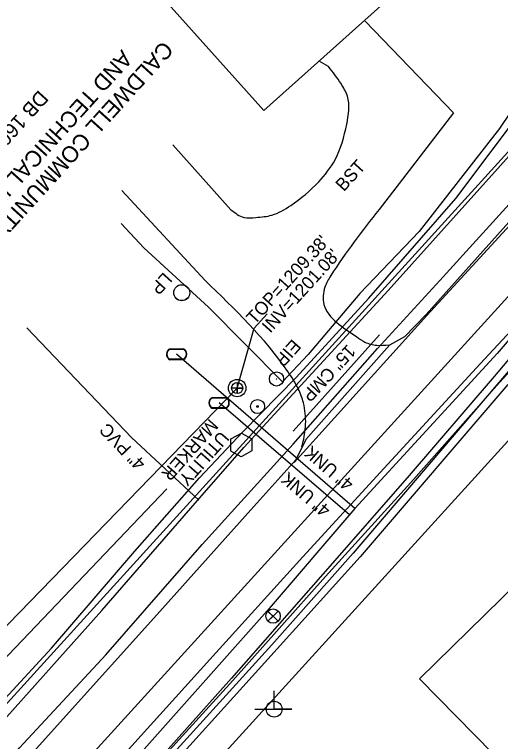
# Model space of a CAD drawing. Extents: x 1263837 to 1268319, y 770628 to 773628.
# Drawn here: x 1267189.7 to 1267339.7, y 772645 to 772869.3 of the extents above; entities that cross this region are included whole.
import ezdxf

# ---------------------------------------------------------------- set-up
doc = ezdxf.new("R2010")
doc.units = 0
for name, color, linetype in [('CTL Primary Horizontal and Vertical CELL', 7, 'Continuous'), ('Exist Building', 7, 'Continuous'), ('Exist Property Deed Book Text', 7, 'Continuous'), ('Exist Property Iron Pin Text', 7, 'Continuous'), ('Exist Roads EOT Text', 7, 'Continuous'), ('Exist Utilities Gas UG Line SUE LOS B', 7, 'Continuous'), ('Exist Utilities Gas UG Line SUE LOS B Text', 7, 'Continuous'), ('Exist Utilities Other Located Object CELL', 7, 'Continuous'), ('Exist Utilities Other Located Object Text', 7, 'Continuous'), ('Exist Utilities Other Pole CELL', 7, 'Continuous'), ('Exist Utilities Other Pole With Base Text', 7, 'Continuous'), ('Exist Utilities Power Joint Use Telephone CELL', 7, 'Continuous'), ('Exist Utilities Power UG Cable SUE LOS B', 7, 'Continuous'), ('Exist Utilities Telephone UG Cable SUE LOS B', 7, 'Continuous'), ('Exist Utilities Telephone UG FO SUE LOS B', 7, 'Continuous'), ('Exist Utilities Water Meter CELL', 7, 'Continuous'), ('Exist Utilities Water UG Line SUE LOS B', 7, 'Continuous'), ('Exist Utilities Water UG Line SUE LOS B Text', 7, 'Continuous'), ('Exist Utilities Water Valve CELL', 7, 'Continuous'), ('Pattern 2', 7, 'Continuous'), ('Prop Conc 4in Sidewalk', 7, 'Continuous'), ('Prop Drainage Structure Pipe RCP 15in Class III Label', 7, 'Continuous'), ('Prop Drainage Structure Pipe RCP 24in Class III Label', 7, 'Continuous'), ('Prop Earthen Structure Base Ditch Special Cut with Rip Rap Detail CELL', 7, 'Continuous'), ('Prop Horizontal Alignment', 7, 'Continuous'), ('Prop Retaining Wall', 7, 'Continuous'), ('Prop SS Fill Text', 7, 'Continuous'), ('Prop SS Transition Line', 7, 'Continuous'), ('Prop WCR CELL', 7, 'Continuous'), ('Scratch_Level_2', 7, 'Continuous'), ('Scratch_Level_5', 7, 'Continuous')]:
    doc.layers.add(name, color=color, linetype=linetype)

# ---------------------------------------------------------------- blocks, each defined once
blk = doc.blocks.new('EXIST UTILITIES SANITARY SEWER MANHOLE')
at = {"layer": 'Prop WCR CELL'}
blk.add_lwpolyline([(0, 0.03425), (0, -0.03425), (0, 0), (0.03425, 0), (-0.03425, 0)], dxfattribs=at)
for radius in [0.05389, 0.03425]:
    blk.add_circle((0, 0), radius, dxfattribs=at)
blk = doc.blocks.new('EXIST PROPERTY IRON PIN')
at = {"layer": 'Prop Conc 4in Sidewalk'}
for radius in [0.0441, 0.00141]:
    blk.add_circle((0, 0), radius, dxfattribs=at)
blk = doc.blocks.new('EXIST UTILITIES OTHER POLE')
at = {"layer": 'Exist Utilities Other Pole CELL'}
blk.add_circle((0, 0), 0.0493, dxfattribs=at)
blk = doc.blocks.new('EXIST UTILITIES POWER JOINT USE TELEPHONE')
at = {"layer": 'Exist Utilities Power Joint Use Telephone CELL'}
blk.add_line((0, 0), (0, 0), dxfattribs=at)
blk.add_lwpolyline([(-0.1188, 0), (0.108, -0.0008), (0, -0.0004), (0, 0.1125)], dxfattribs=at)
blk.add_circle((0, 0.0001), 0.049, dxfattribs=at)
blk = doc.blocks.new('EXIST UTILITIES WATER METER')
at = {"layer": 'Exist Utilities Water Meter CELL'}
blk.add_line((0, 0), (0, 0), dxfattribs=at)
for points in [[(-0.0408, 0.034), (0.0408, 0.034)], [(-0.0408, 0.0312), (0.0408, 0.0312)], [(0.0408, -0.0312), (-0.0413, -0.0312)], [(0.0408, -0.034), (-0.0413, -0.034)]]:
    blk.add_lwpolyline(points, dxfattribs=at)
for centre, radius, start, end in [((-0.0261, -0.0001), 0.0371, 113.178, 245.9794), ((-0.0259, -0.0001), 0.0347, 115.3009, 243.7824), ((0.0259, 0), 0.0371, 293.6483, 66.3084), ((0.0261, 0), 0.0345, 295.1272, 64.8728)]:
    blk.add_arc(centre, radius, start, end, dxfattribs=at)
blk = doc.blocks.new('EXIST UTILITIES WATER VALVE')
at = {"layer": 'Exist Utilities Water Valve CELL'}
blk.add_lwpolyline([(0.0315, 0.0315), (-0.0315, -0.0315), (0, 0), (0.0315, -0.0315), (-0.0315, 0.0315)], dxfattribs=at)
blk.add_circle((0, 0), 0.0445, dxfattribs=at)
blk = doc.blocks.new('CTL PRIMARY HORIZONTAL AND VERTICAL')
at = {"layer": 'CTL Primary Horizontal and Vertical CELL'}
blk.add_line((0, 0), (0, 0), dxfattribs=at)
blk.add_lwpolyline([(-0.0646, 0.0374), (0.0004, 0.0737), (0.0654, 0.0379), (0.0644, -0.0366), (-0.0006, -0.0743), (-0.0646, -0.0381)], close=True, dxfattribs=at)

msp = doc.modelspace()

# ---------------------------------------------------------------- linework, layer by layer
at = {"layer": 'Exist Building'}
for p, q in [((1267116.32, 773007.6), (1267266.64, 772839.68)), ((1267266.64, 772839.68), (1267319.09, 772886.64)), ((1267373.44, 772721.88), (1267314.68, 772664.3)), ((1267314.68, 772664.3), (1267337.41, 772641.1))]:
    msp.add_line(p, q, dxfattribs=at)
at = {"layer": 'Exist Utilities Gas UG Line SUE LOS B'}
msp.add_line((1267246.59, 772719.43), (1267225.83, 772738.76), dxfattribs=at)
for points in [[(1267020.79, 772462.03), (1267045.96, 772488.76), (1267078.13, 772529.13), (1267092.32, 772547.17), (1267130.56, 772588.01), (1267171.7, 772635.15), (1267216.72, 772685.42), (1267246.23, 772719.28), (1267260.5, 772735.72), (1267305.1, 772784.15), (1267347.02, 772830.88), (1267365.09, 772851.17), (1267410.96, 772900.49)], [(1267225.83, 772738.76), (1267193.52, 772772.66)]]:
    msp.add_lwpolyline(points, dxfattribs=at)
at = {"layer": 'Exist Utilities Other Located Object CELL'}
for radius in [2.18, 0.24]:
    msp.add_circle((1267264.73, 772748.33), radius, dxfattribs=at)
at = {"layer": 'Exist Utilities Power UG Cable SUE LOS B'}
msp.add_lwpolyline([(1267355.22, 772865.4), (1267354.08, 772858.31), (1267346.45, 772844.52), (1267339.36, 772834.19), (1267314.65, 772802.37), (1267296.34, 772783.18), (1267280.39, 772764.34), (1267272.49, 772755.97), (1267249.62, 772779.04), (1267229.62, 772797.32), (1267222.61, 772804.79)], dxfattribs=at)
at = {"layer": 'Exist Utilities Telephone UG Cable SUE LOS B'}
for points in [[(1267100.22, 772481.78), (1267112, 772553.94), (1267138.91, 772584.09), (1267164.9, 772612.71), (1267191.24, 772643.02), (1267217.96, 772671.68), (1267247.67, 772705.71), (1267275.74, 772736.7), (1267301.71, 772766.25), (1267320.99, 772787.2), (1267344.49, 772813.03), (1267370.25, 772842.85), (1267398.38, 772873.52), (1267417.15, 772894.89)], [(1267342, 772755.1), (1267296.41, 772701.93), (1267270.82, 772673.52), (1267227.47, 772625.56), (1267187.97, 772581.82), (1267145.3, 772538.42), (1267104.22, 772490.18)]]:
    msp.add_lwpolyline(points, dxfattribs=at)
at = {"layer": 'Exist Utilities Telephone UG FO SUE LOS B'}
for points in [[(1267175.93, 772646.52), (1267201.12, 772673.74), (1267226.91, 772703.72), (1267246.83, 772726.29), (1267260.18, 772740.54), (1267276.64, 772757.26), (1267299.07, 772781.82), (1267325.98, 772812.5), (1267348.02, 772842.01), (1267367.93, 772860.93), (1267390.85, 772882.02)], [(1267440.93, 772873.36), (1267435.42, 772866.83), (1267419.98, 772848.71), (1267378.68, 772801.72), (1267341.57, 772758.54), (1267294.3, 772703.09), (1267269.18, 772674.73), (1267225.77, 772626.96), (1267186.33, 772583.06), (1267145.92, 772540.78), (1267094.71, 772485.45)]]:
    msp.add_lwpolyline(points, dxfattribs=at)
at = {"layer": 'Exist Utilities Water UG Line SUE LOS B'}
for p, q in [((1267294.81, 772716.88), (1267239.77, 772764.48)), ((1267293.14, 772714.94), (1267252.88, 772749.46)), ((1267267.69, 772685.26), (1267269.52, 772683.64)), ((1267268.01, 772684.98), (1267269.38, 772683.74))]:
    msp.add_line(p, q, dxfattribs=at)
for points in [[(1267437.01, 772876.91), (1267431.97, 772871.23), (1267414.44, 772853.3), (1267373.39, 772805.21), (1267338.68, 772764.66), (1267294.81, 772716.88), (1267267.74, 772685.31), (1267223.19, 772635.21), (1267181.65, 772588.34), (1267140.87, 772542.79), (1267094.63, 772491.21)], [(1267015.09, 772480.76), (1267121.94, 772602.68), (1267236.76, 772722.91)]]:
    msp.add_lwpolyline(points, dxfattribs=at)
at = {"layer": 'Pattern 2'}
msp.add_lwpolyline([(1267258.45, 772754.02), (1267263.69, 772772.48), (1267267.72, 772776.92)], dxfattribs=at)
at = {"layer": 'Prop Drainage Structure Pipe RCP 15in Class III Label'}
msp.add_line((1267302.35, 772770.44), (1267275.71, 772740.68), dxfattribs=at)
at = {"layer": 'Prop Horizontal Alignment'}
for p, q in [((1267380.31, 772869.08), (1266850.44, 772285.9)), ((1267424.71, 772828.73), (1266891.83, 772242.23))]:
    msp.add_line(p, q, dxfattribs=at)
at = {"layer": 'Prop SS Fill Text'}
for p, q in [((1267286.67, 772853.24), (1267283.79, 772854.95)), ((1267238.57, 772829.11), (1267256.54, 772809.07)), ((1267248.53, 772787.24), (1267222.84, 772815.04))]:
    msp.add_line(p, q, dxfattribs=at)
for points in [[(1267417.78, 772890.69), (1267388.91, 772857.24), (1267346.69, 772810.15), (1267316.76, 772776.69), (1267310.14, 772769.86), (1267305.46, 772767.25), (1267286.84, 772746.29), (1267279.63, 772738.12), (1267276.53, 772731.91), (1267262.67, 772716.41), (1267233.63, 772684.01), (1267204.74, 772651.92), (1267177.02, 772621.14)], [(1267297.98, 772867.26), (1267325.23, 772839.01), (1267302.27, 772809.18)], [(1267415.39, 772834.97), (1267400.81, 772818.54), (1267379.05, 772793.9), (1267370.35, 772789.46), (1267339.46, 772755.79), (1267312.08, 772724.87), (1267285.74, 772695.86), (1267257.15, 772663.77), (1267228.14, 772631.87), (1267200.2, 772600.69), (1267172.19, 772569.47)]]:
    msp.add_lwpolyline(points, dxfattribs=at)
for points in [[(1267256.54, 772809.07), (1267260.58, 772806.71), (1267264.21, 772806.7), (1267269.18, 772807.41), (1267274.98, 772810.4), (1267283.62, 772817.68), (1267288.65, 772824.48), (1267292.25, 772835.45), (1267292.46, 772844.12), (1267290.5, 772848), (1267286.67, 772853.24)], [(1267302.27, 772809.18), (1267287.34, 772788.72), (1267285.52, 772785.19), (1267285.24, 772779.86), (1267295.24, 772769.9), (1267297.88, 772768.22), (1267301.56, 772767.24), (1267305.2, 772767.4)], [(1267278.4, 772735.92), (1267278.63, 772736.76), (1267279.58, 772742.89), (1267278.9, 772749.49), (1267277.3, 772753.77), (1267274.11, 772759.09), (1267248.53, 772787.24)]]:
    msp.add_spline(points, degree=3, dxfattribs=at)
at = {"layer": 'Prop SS Transition Line'}
for points in [[(1267454.26, 772928.56), (1267419.78, 772888.78), (1267390.33, 772856.01), (1267347.36, 772809.42), (1267317, 772776.45), (1267288.45, 772744.83), (1267276.08, 772731.08)], [(1267473.1, 772914.44), (1267437.91, 772874.02), (1267408.48, 772840.83), (1267367.79, 772793.17), (1267337.72, 772757.59), (1267310.91, 772726.31), (1267284.91, 772696.55), (1267256.66, 772664.46), (1267227.77, 772632.12)], [(1267395.07, 772827.56), (1267364.93, 772795.4), (1267333.45, 772761.5), (1267304.93, 772730.59), (1267278.73, 772701.98), (1267250.02, 772670.21), (1267221.06, 772638.24), (1267193.05, 772607.16), (1267162.88, 772573.94), (1267133.95, 772541.76), (1267103.89, 772508.37), (1267089.63, 772492.49), (1267063.41, 772464.33), (1267037.06, 772433.84), (1267009.94, 772404.86), (1266986.14, 772378.32), (1266959.27, 772348.06), (1266929.7, 772314.83), (1266900.08, 772282.12), (1266879.74, 772258.85), (1266856.83, 772233.08), (1266828.41, 772200.91)]]:
    msp.add_lwpolyline(points, dxfattribs=at)
at = {"layer": 'Scratch_Level_2'}
msp.add_line((1267402.51, 772848.9), (1266783.44, 772167.55), dxfattribs=at)
at = {"layer": 'Scratch_Level_5'}
msp.add_line((1266999.68, 772487.46), (1267258.45, 772754.02), dxfattribs=at)

# ---------------------------------------------------------------- block references
at = {"layer": 'CTL Primary Horizontal and Vertical CELL', "xscale": 50, "yscale": 50}
msp.add_blockref('CTL PRIMARY HORIZONTAL AND VERTICAL', (1267259.75, 772736.47), dxfattribs=at)
msp.add_blockref('CTL PRIMARY HORIZONTAL AND VERTICAL', (1267259.75, 772736.47), dxfattribs=at)
at = {"layer": 'Exist Utilities Other Pole CELL', "xscale": 50, "yscale": 50}
for p in [(1267241.35, 772783.47), (1267241.35, 772783.45)]:
    msp.add_blockref('EXIST UTILITIES OTHER POLE', p, dxfattribs=at)
at = {"layer": 'Exist Utilities Power Joint Use Telephone CELL', "xscale": 50, "yscale": 50}
msp.add_blockref('EXIST UTILITIES POWER JOINT USE TELEPHONE', (1267269.88, 772654.93), dxfattribs=at)
at = {"layer": 'Exist Utilities Water Meter CELL', "xscale": 50, "yscale": 50}
for p in [(1267239.77, 772764.48), (1267252.88, 772749.46)]:
    msp.add_blockref('EXIST UTILITIES WATER METER', p, dxfattribs=at)
at = {"layer": 'Exist Utilities Water Valve CELL', "xscale": 50, "yscale": 50}
msp.add_blockref('EXIST UTILITIES WATER VALVE', (1267269.52, 772683.64), dxfattribs=at)
at = {"layer": 'Prop Conc 4in Sidewalk', "xscale": 50, "yscale": 50}
msp.add_blockref('EXIST PROPERTY IRON PIN', (1267270.59, 772756.85), dxfattribs=at)
at = {"layer": 'Prop WCR CELL', "xscale": 50, "yscale": 50}
msp.add_blockref('EXIST UTILITIES SANITARY SEWER MANHOLE', (1267258.45, 772754.02), dxfattribs=at)

# ---------------------------------------------------------------- texts
at = {"layer": 'Exist Property Deed Book Text'}
msp.add_text('DB 1603 PG 1447', height=4.5, rotation=227.8377, dxfattribs=at).set_placement((1267197.25, 772846.24))
at = {"layer": 'Exist Property Iron Pin Text'}
msp.add_text('EIP', height=4, rotation=228.389, dxfattribs=at).set_placement((1267275.51, 772769.38))
at = {"layer": 'Exist Roads EOT Text'}
msp.add_text('BST', height=4, rotation=47.742, dxfattribs=at).set_placement((1267291.36, 772814.46))
at = {"layer": 'Exist Utilities Gas UG Line SUE LOS B Text'}
msp.add_text('4" PVC', height=4, rotation=133.6318, dxfattribs=at).set_placement((1267230.47, 772731))
at = {"layer": 'Exist Utilities Other Located Object Text'}
for s, p in [('MARKER', (1267249.96, 772744.79)), ('UTILITY', (1267253.3, 772741.03))]:
    msp.add_text(s, height=4, rotation=228.4866, dxfattribs=at).set_placement(p)
at = {"layer": 'Exist Utilities Other Pole With Base Text'}
msp.add_text('LP', height=4, rotation=227.742, dxfattribs=at).set_placement((1267235.78, 772790.02))
at = {"layer": 'Exist Utilities Water UG Line SUE LOS B Text'}
for rotation, p in [(139.1453, (1267294.74, 772724.94)), (139.3888, (1267287.59, 772716.87))]:
    msp.add_text('4" UNK', height=4, rotation=rotation, dxfattribs=at).set_placement(p)
at = {"layer": 'Prop Drainage Structure Pipe RCP 24in Class III Label'}
msp.add_text('15" CMP', height=4, rotation=227.3183, dxfattribs=at).set_placement((1267292.5, 772767.74))
at = {"layer": 'Prop Earthen Structure Base Ditch Special Cut with Rip Rap Detail CELL'}
for s, p in [('CALDWELL COMMUNITY COLLEGE', (1267235.48, 772861.49)), ('AND TECHNICAL INSTITUTE', (1267222.84, 772858.7))]:
    msp.add_text(s, height=5, rotation=227.8377, dxfattribs=at).set_placement(p)
at = {"layer": 'Prop Retaining Wall'}
for s, p in [("TOP=1209.38'", (1267263.87, 772773.41)), ("INV=1201.08'", (1267268.67, 772770.76))]:
    msp.add_text(s, height=4, rotation=47.742, dxfattribs=at).set_placement(p)

doc.saveas('drawing.dxf')
